Omron CX-Programmer project NuevoProyecto (CX-Programmer 9.50)

# PLC NewPLC1: CQM1 CPU21

## Global symbols (name address type ; comment)
15.00 BOOL  ; FSS1

## Program P8_2 (no task)
Local symbols
CIN1_De 100.04 BOOL
CIN1_Iz 100.03 BOOL
CIN2 100.05 BOOL
D 100.06 BOOL
ELA 100.00 BOOL
ELB 100.01 BOOL
ELC 100.02 BOOL
Etapa_0 10.00 BOOL
Etapa_1 10.01 BOOL
Etapa_10 10.10 BOOL
Etapa_2 10.02 BOOL
Etapa_21 20.01 BOOL
Etapa_22 20.02 BOOL
Etapa_23 20.03 BOOL
Etapa_3 10.03 BOOL
Etapa_4 10.04 BOOL
Etapa_5 10.05 BOOL
Etapa_6 10.06 BOOL
Etapa_7 10.07 BOOL
Etapa_8 10.08 BOOL
Etapa_9 10.09 BOOL
Etapa_E20 20.00 BOOL
Etapa_S20 20.04 BOOL
F1 0.02 BOOL
F2 0.03 BOOL
FSS_1 15.00 BOOL
S_1 0.01 BOOL
m 0.00 BOOL

### Section Sección1_Programa_principal
; Programa principal (Etapas 0 ... 10)

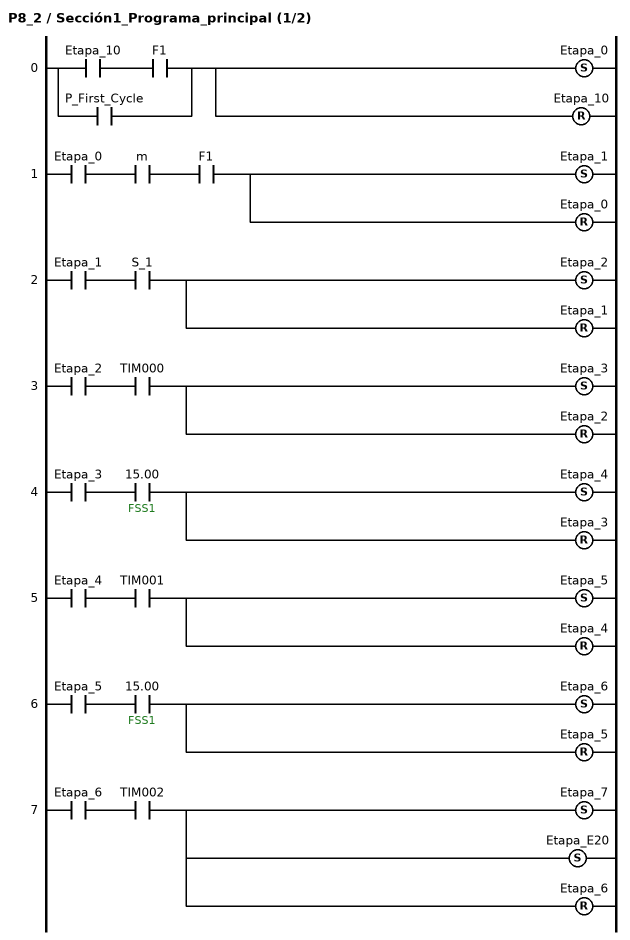
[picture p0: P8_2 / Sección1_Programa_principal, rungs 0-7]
; rung 0
LD Etapa_10
AND F1
OR P_First_Cycle
SET Etapa_0
RSET Etapa_10
; rung 1
LD Etapa_0
AND m
AND F1
SET Etapa_1
RSET Etapa_0
; rung 2
LD Etapa_1
AND S_1
SET Etapa_2
RSET Etapa_1
; rung 3
LD Etapa_2
AND TIM000
SET Etapa_3
RSET Etapa_2
; rung 4
LD Etapa_3
AND 15.00  ; FSS1
SET Etapa_4
RSET Etapa_3
; rung 5
LD Etapa_4
AND TIM001
SET Etapa_5
RSET Etapa_4
; rung 6
LD Etapa_5
AND 15.00  ; FSS1
SET Etapa_6
RSET Etapa_5
; rung 7
LD Etapa_6
AND TIM002
SET Etapa_7
SET Etapa_E20
RSET Etapa_6

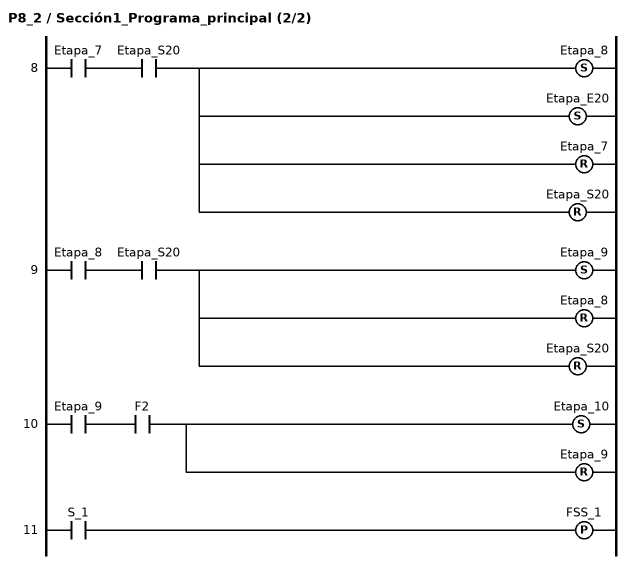
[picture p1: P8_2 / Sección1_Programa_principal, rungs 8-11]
; rung 8
LD Etapa_7
AND Etapa_S20
SET Etapa_8
SET Etapa_E20
RSET Etapa_7
RSET Etapa_S20
; rung 9
LD Etapa_8
AND Etapa_S20
SET Etapa_9
RSET Etapa_8
RSET Etapa_S20
; rung 10
LD Etapa_9
AND F2
SET Etapa_10
RSET Etapa_9
; rung 11
LD S_1
DIFU(13) FSS_1

### Section Sección2_Macroetapa
; Macroetapa

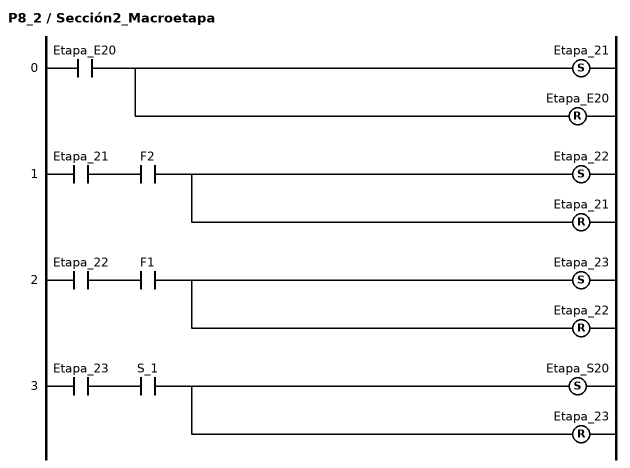
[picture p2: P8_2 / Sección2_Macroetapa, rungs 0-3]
; rung 0
LD Etapa_E20
SET Etapa_21
RSET Etapa_E20
; rung 1
LD Etapa_21
AND F2
SET Etapa_22
RSET Etapa_21
; rung 2
LD Etapa_22
AND F1
SET Etapa_23
RSET Etapa_22
; rung 3
LD Etapa_23
AND S_1
SET Etapa_S20
RSET Etapa_23

### Section Sección3_Temporizadores

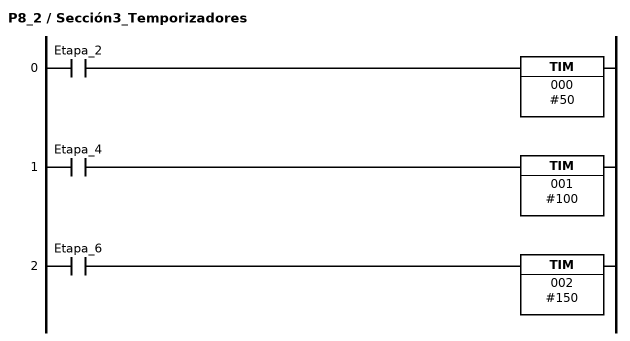
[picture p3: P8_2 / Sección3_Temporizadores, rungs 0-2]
; rung 0
LD Etapa_2
TIM 000 #50
; rung 1
LD Etapa_4
TIM 001 #100
; rung 2
LD Etapa_6
TIM 002 #150

### Section Sección4_Salidas
; Salidas

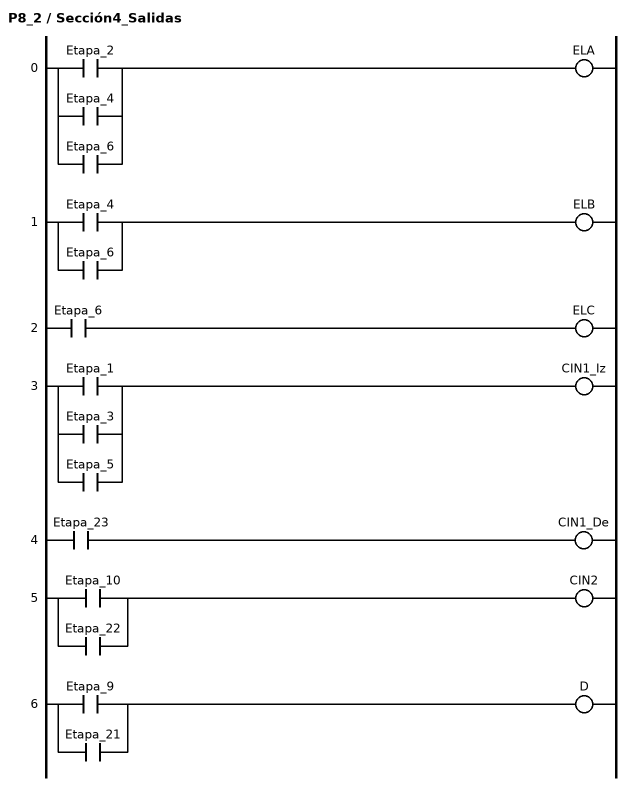
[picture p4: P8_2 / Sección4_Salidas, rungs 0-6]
; rung 0
LD Etapa_2
OR Etapa_4
OR Etapa_6
OUT ELA
; rung 1
LD Etapa_4
OR Etapa_6
OUT ELB
; rung 2
LD Etapa_6
OUT ELC
; rung 3
LD Etapa_1
OR Etapa_3
OR Etapa_5
OUT CIN1_Iz
; rung 4
LD Etapa_23
OUT CIN1_De
; rung 5
LD Etapa_10
OR Etapa_22
OUT CIN2
; rung 6
LD Etapa_9
OR Etapa_21
OUT D

### Section Sección5_END
; rung 0
END(01)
